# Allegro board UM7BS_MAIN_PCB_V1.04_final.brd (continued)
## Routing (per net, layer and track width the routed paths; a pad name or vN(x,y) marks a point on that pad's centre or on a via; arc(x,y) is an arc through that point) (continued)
N16952168: length 1.8
  TOP w0.102: CN9.38 v1(78.08,43.92)
  BOTTOM w0.102: R560.2 v1(78.08,43.92)
N16952170: length 1.8
  TOP w0.102: CN9.68 80.37,36.42 v1(80.46,36.32)
  BOTTOM w0.102: R561.2 80.56,36.42 v1(80.46,36.32)
N16952426: length 7.2
  TOP w0.124: C296.1 90.29,46.04 89.98,45.73 89.55,45.73 89.28,45.46 89.28,42.29 88.53,41.54 87.94,41.54 87.82,41.67 CN9.47
N16952428: length 7.3
  TOP w0.124: C171.1 89.77,47.1 88.89,47.1 88.38,46.58 88.38,43.27 88.15,43.04 87.77,43.04 87.64,43.17 CN9.41
N16952430: length 7.2
  TOP w0.124: CN9.49 87.82,41.17 87.94,41.29 88.63,41.29 89.53,42.18 89.53,45.35 89.65,45.48 90.07,45.48 C312.1
N16952432: length 7.1
  TOP w0.124: C263.1 89,46.85 88.63,46.48 88.63,43.16 88.25,42.79 87.82,42.79 87.7,42.67 CN9.43
N16952456: length 2.2
  TOP w0.102: CN9.69 89.09,36.17 R564.1
N16968122: length 16.8
  TOP w0.508: v1(111.5,88.7) R707.2 ; R707.2 R663.2 R495.2 R3100.2 ; R707.2 112.54,89.71 112.89,90.06 Q95.2
  BOTTOM w0.305: R3091.1 115.8,83.6 112.75,86.65 112.75,87.44 v1(111.5,88.7)
N16968198: length 12.8
  TOP w0.406: v1(112.61,91.07) 112.61,91.5 114.33,93.21 Q95.1
  BOTTOM w0.305: R606.2 115.6,84.48 113.43,86.65 113.43,88.91 112.61,89.73 v1(112.61,91.07)
N16969285: length 5.5
  BOTTOM w0.406: J5.5 109.26,95.31 108.84,95.72 107.7,95.72 106.12,94.15 R367.1
N16969287: length 4.7
  BOTTOM w0.406: J5.6 107.3,94.33 106.31,93.33 104.97,93.33 104.62,93.69 R3097.1
N16970384: length 4.2
  TOP w0.305: R3098.1 114.12,81.12 CN40.1 115.6,81.11 118.31,81.11 R681.2
N16970389: length 4.3
  TOP w0.305: R636.2 118.44,83.12 CN40.3 114.12,83.12 R465.1
N16970394: length 4.4
  TOP w0.305: R756.2 115.61,85.12 CN40.5 114.12,85.12 R466.1
N16970402: length 4.6
  TOP w0.305: R755.1 117.15,86.61 116.65,87.12 115.61,87.12 CN40.7 115.6,87.12 R3099.1
N16987716: length 1.3
  TOP w0.102: R509.2 Q16.3
N16987732: length 8.1
  TOP w0.102: R509.1 100.31,10.12 100.72,9.71 104.27,9.71 105.48,8.5 LED2.2
N17079846: length 3.8
  TOP w1.016: v2(99.24,57.46) 99.48,57.23 CN3.P7
  BOTTOM w0.762: v2(99.24,57.46) 99.59,57.46 R748.2
N17211775: length 3.4
  BOTTOM w0.102: R467.2 45.06,57.63 45.06,58.25 45.47,58.66 U31.67
N17343515: length 2.8
  TOP w0.102: R170.2 180.23,87.06 179.98,87.31 179.98,87.69 179.54,88.13 U9.4
N17343556: length 2.5
  TOP w0.101: R578.1 170.18,88.02 170.75,88.02 170.86,88.13 U9.25
N17343558: length 2.6
  TOP w0.101: U9.26 170.97,87.48 170.66,87.79 170,87.79 R577.1
N17343560: length 1.4
  TOP w0.102: R175.2 179.87,94.63 U9.14
N17343567: length 2.1
  TOP w0.305: FB2.2 170.57,93.98 U9.16
N17343572: length 2.6
  TOP w0.203: R173.1 169.84,91.67 170.85,92.68 U9.18
N17343578: length 2.4
  TOP w0.305: U9.23 170.99,89.43 170.52,89.9 R171.1
N17555300: length 1.9
  BOTTOM w0.203: U53.4 155.01,52.26 R3107.2 R3106.1
N17555409: length 1.1
  BOTTOM w0.305: U53.6 151.39,50.64 R3108.1
N17556891: length 1.9
  BOTTOM w0.254: U2525.4 165.54,72.27 R746.1 166.51,72.44 R3113.2
N17556904: length 2.2
  BOTTOM w0.254: U2525.5 166.04,71.44 166.85,71.44
  BOTTOM w0.305: R3109.2 166.85,71.44
N17556998: length 1.3
  BOTTOM w0.305: U2525.6 166.57,68.79 166.95,69.17 R3112.1
N169681891: length 0.9
  BOTTOM w0.305: R3093.2 C727.2

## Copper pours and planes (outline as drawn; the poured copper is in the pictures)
+V1.2A on TOP (solid shape): 166.9,28.21 166.9,27.46 166.85,27.42 166.42,27.42 166.3,27.3 166.29,27.3 165.07,26.09 165.07,26.07 164.97,25.97 164.97,25.87 164.85,25.74 164.08,25.74 163.96,25.87 163.96,25.96 163.97,26.03 163.98,26.09 163.98,26.36 164.15,26.54 164.18,26.53 164.24,26.53 164.3,26.55 164.48,26.55 166.17,28.23 166.87,28.23
+V1.2A on BOTTOM (solid shape): 166.16,26.46 166.16,25.83 166.03,25.7 164.33,25.7 164.17,25.86 164.17,26.22 164.8,26.84 165.78,26.84
+V1.05A on TOP (solid shape): 164.88,13.93 167.51,13.93 167.9,13.55 167.9,10.9 167.8,10.8 163.9,10.8 162.79,11.91 162.79,14.48 162.99,14.68 164.14,14.68
+V1.05A on TOP (solid shape): 188.1,60.39 188.1,60.14 187.34,59.37 187.09,59.37 187.03,59.44 186.58,59.88 186.58,60.01 187.09,60.52 187.98,60.52
+V1.05A on TOP (solid shape): 188.1,65.09 188.1,64.84 187.98,64.71 187.09,64.71 186.6,65.2 186.6,65.24 186.58,65.28 186.58,65.34 186.71,65.47 186.71,65.85 186.58,65.98 186.58,66.11 186.71,66.23 186.96,66.23
+V1.05A on TOP (solid shape): 174.82,55.05 174.92,55.04 175.01,55.05 175.02,55.06 175.28,55.06 175.59,54.74 175.59,54.73 175.62,54.66 175.66,54.6 175.66,54.29 175.53,54.17 174.64,54.17 174.46,54.35 174.46,54.36 174.4,54.47 174.3,54.54 174.28,54.55 174.26,54.57 174.26,54.93 174.39,55.06 174.82,55.06
+V1.05A on TOP (solid shape): 179.46,61.28 179.48,61.27 179.49,61.26 179.75,61.14 180,61.26 180.01,61.27 180.04,61.28 180.23,61.28 180.36,61.15 180.36,60.14 180.05,59.83 179.99,59.8 179.94,59.76 179.92,59.76 179.72,59.76 179.21,60.26 179.21,61.15 179.34,61.28
+V1.05A on TOP (solid shape): 181.88,67.25 181.88,67.12 181.75,66.99 181.75,66.61 181.99,66.38 181.99,66.34 182.01,66.31 182.01,65.72 182.77,64.96 182.77,64.84 182.76,64.82 182.74,64.8 182.66,64.75 182.6,64.67 182.53,64.62 182.44,64.65 181.37,65.72 181.25,65.72 180.87,65.34 180.87,65.09 181.25,64.71 181.25,64.2 180.99,63.95 180.87,63.95 180.48,64.33 180.48,64.96 180.04,65.41 180.01,65.45 179.98,65.5 179.98,65.51 179.98,65.72 181.63,67.38 181.75,67.38
+V1.05A on BOTTOM (solid shape): 170.24,48.86 170.24,47.49 170.16,47.41 170.16,44.25 169.83,43.92 167.84,43.92 167.69,44.06 167.69,49.8 167.86,49.97 169.13,49.97
+V1.05A on BOTTOM (solid shape): 179.99,63.02 179.99,62.1 179.78,61.89 179.57,61.89 179.31,61.63 178.82,61.63 178.74,61.71 178.74,62.21 178.86,62.33 178.86,63.59 178.96,63.69 179.31,63.69
+V1.05A on BOTTOM (solid shape): 164.71,14.87 164.81,14.8 164.78,14.69 164.83,14.13 165.36,14.34 165.37,14.35 166.34,14.35 166.37,14.32 166.37,11.53 166.15,11.31 163.18,11.31 163.07,11.42 163.07,14.56 163.37,14.87
+V1.05A on LAY3 (solid shape): outline of 1400 points within 157.66,11.65 166.1,31.05
+V1.05A on LAY4 (solid shape): outline of 404 points within 158.47,27.78 169.86,49.4
+V1.05A on LAY4 (solid shape): outline of 964 points within 180.99,59.63 188.23,72.96
+V1.05A on VCC5 (solid shape): outline of 4249 points within 168.56,43.92 182.29,68.54
+V1.5S on BOTTOM (solid shape): 145.69,44.06 145.69,41.64 145.57,41.51 143.77,41.51 143.69,41.59 143.69,42.34 143.77,42.42 144.28,42.42 144.38,42.52 144.38,43.95 144.6,44.17 145.58,44.17
+V1.8A on TOP (solid shape): 154.41,47.45 155.05,47.45 155.18,47.32 155.18,45.67 154.8,45.29 153.91,45.29 153.27,45.92 152.64,45.92 152.51,46.05 152.51,47.7 152.64,47.83 154.03,47.83
+V1.8A on TOP (solid shape): 156.73,14.06 156.73,12.07 155.64,10.97 154.95,10.97 153.13,12.79 153.13,14.15 153.39,14.42 153.47,14.45 153.54,14.41 153.91,14.31 154.15,14.62 154.18,14.69 154.25,14.71 156.08,14.71
+V1.8A on BOTTOM (solid shape): 156.8,13.82 156.81,13.82 156.81,11.57 156.6,11.36 153.59,11.36 153.39,11.56 153.39,13.83 153.55,13.98 156.63,13.98
+V1.8A on BOTTOM (solid shape): 175.14,50.26 175.14,49.01 175.1,48.96 174.65,48.96 174.62,48.99 174.62,49.88 174.39,50.11 172.8,50.11 172.58,49.88 172.58,49.08 172.53,49.03 172.09,49.03 172.01,49.1 172.02,49.11 172.02,49.93 172.61,50.52 174.88,50.52
+V1.8A on BOTTOM (solid shape): outline of 318 points within 144.99,43.25 165.64,69.1
+V1.8A on LAY3 (solid shape): outline of 1597 points within 143.92,11.64 155.92,44.79
+V1.8A on LAY3 (solid shape): outline of 2990 points within 178.96,41.21 193.56,69.81
+V1.8A on LAY4 (solid shape): outline of 1638 points within 170.19,57.09 182.01,65.65
+V1.8A_SPI on TOP (solid shape): 157.08,49.15 157.08,47.19 156.19,46.3 156.19,43 155.81,42.62 152.64,42.62 152.51,42.75 152.51,44.42 152.56,44.46 154.73,44.46 155.43,45.16 155.43,47.96 155.18,48.21 154.41,48.21 154.29,48.34 154.29,49.35 154.35,49.42 156.81,49.42
+V1.15A on TOP (solid shape): 165.36,29.94 165.36,29.12 165.3,29.06 164.53,29.06 164.37,29.21 164.37,29.7 164.17,29.91 163.11,29.91 162.85,30.17 162.85,30.7 162.94,30.79 164.51,30.79
+V1.15A on TOP (solid shape): 187.31,63.6 187.36,63.54 187.47,63.44 187.47,63.31 187.34,63.18 186.96,63.18 186.64,63.51 186.6,63.55 186.55,63.59 186.34,63.8 186.34,63.82 186.3,63.92 186.22,64 186.2,64.02 186.2,64.05 186.2,64.2 186.33,64.33 186.58,64.33
+V1.15A on TOP (solid shape): 186.07,66.36 186.07,66.23 186.2,66.11 186.33,66.11 186.48,65.95 186.48,65.94 186.49,65.92 186.53,65.85 186.57,65.8 186.58,65.78 186.58,65.76 186.58,65.6 186.45,65.47 186.29,65.47 186.27,65.47 186.26,65.49 186.19,65.54 186.1,65.58 186.09,65.58 185.44,66.23 185.44,66.49 185.56,66.61 185.82,66.61
+V1.15A on TOP (solid shape): 186.5,59.76 186.52,59.75 186.54,59.73 186.61,59.67 186.69,59.62 186.7,59.62 187.05,59.27 187.06,59.27 187.47,58.87 187.47,58.76 187.45,58.74 187.44,58.73 187.38,58.69 187.33,58.63 187.31,58.62 187.29,58.61 187.09,58.61 187.04,58.67 187,58.7 186.2,59.5 186.2,59.63 186.33,59.76
+V1.15A on TOP (solid shape): 186.17,67.76 186.19,67.75 186.3,67.67 186.41,67.65 186.44,67.64 186.47,67.62 186.48,67.6 186.49,67.43 186.58,67.3 186.58,67.28 186.58,67.04 186.58,67.02 186.57,67 186.48,66.78 186.57,66.55 186.58,66.54 186.58,66.52 186.58,66.36 186.49,66.27 186.45,66.25 186.42,66.27 185.82,66.87 185.82,66.97 185.9,67.16 185.82,67.34 185.82,67.63 185.95,67.76
+V1.15A on BOTTOM (solid shape): outline of 202 points within 157.42,71.1 174.53,78.37
+V1.15A on BOTTOM (solid shape): outline of 887 points within 183.79,58.23 187.98,71.31
+V1.15A on LAY3 (solid shape): outline of 456 points within 185.44,63.31 188.15,69.41
+V1.15A on LAY4 (solid shape): outline of 807 points within 183.79,66.99 186.83,75
+V1.15S on TOP (solid shape): 165.33,28.46 165.33,27.68 165.24,27.58 164.4,27.58 164.05,27.23 163.88,27.23 163.66,27.01 163.45,27.01 163.39,27.08 163.39,27.99 163.52,28.12 164,28.12 164.41,28.54 165.26,28.54
+V1.24A on TOP (solid shape): 166.89,29.64 166.89,28.65 166.83,28.59 165.7,28.59 165.59,28.7 165.59,29.58 165.69,29.68 166.85,29.68
+V1.24A on TOP (solid shape): 180.68,67.76 180.7,67.75 180.72,67.74 180.92,67.65 181.12,67.74 181.14,67.75 181.16,67.76 181.37,67.76 181.5,67.63 181.5,67.5 180.99,66.99 180.87,66.99 180.61,67.25 180.48,67.25 180.23,66.99 180.1,66.99 179.98,67.12 179.98,67.25 180.48,67.76
+V1.24A on TOP (solid shape): 183.15,66.87 183.53,66.87 183.66,66.99 183.79,66.99 184.17,66.61 184.22,66.54 184.28,66.5 184.29,66.49 184.29,66.36 184.17,66.23 183.93,66.23 183.91,66.24 183.9,66.25 183.66,66.35 183.42,66.25 183.4,66.24 183.38,66.23 183.15,66.23 182.26,67.12 182.26,67.25 182.39,67.38 182.64,67.38
+V1.24A on BOTTOM (solid shape): 156.77,53.81 156.77,52.79 156.61,52.63 153.79,52.63 153.71,52.71 153.71,53.87 153.82,53.98 156.6,53.98
+V1.24A on LAY3 (solid shape): outline of 534 points within 179.74,61.79 183.79,68.9
+V1.24A on LAY4 (solid shape): 166.09,29.56 166.09,28.72 165.98,28.61 165.12,28.61 164.99,28.74 164.99,29.59 165.09,29.7 165.96,29.7
+V1.24A on LAY4 (solid shape): outline of 1237 points within 168.91,44.74 180.74,69.15
+V1P8A_EMMC on TOP (solid shape): 185.34,29.92 186.08,29.92 186.16,29.84 186.24,29.33 186.74,29.43 187.26,29.43 187.33,29.37 187.33,28.76 186.79,28.22 186.03,28.22 185.82,28.38 185.56,28.36 185.53,28.34 184.99,28.88 184.99,29.02 184.68,29.33 183.77,29.33 183.67,29.43 183.67,30.3 183.77,30.4 184.86,30.4
+V2P8A_EMMC on TOP (solid shape): outline of 93 points within 179.71,26.37 183.28,30.58
+V3.3A on TOP (solid shape): 156.58,93.16 156.58,90.66 155.97,90.04 153.95,90.04 153.88,90.11 153.88,90.96 154.02,91.1 155.28,91.1 155.53,91.35 155.53,93.24 155.69,93.4 156.34,93.4
+V3.3A on TOP (solid shape): outline of 116 points within 108.14,52.6 116.51,71.83
+V3.3A on BOTTOM (solid shape): 170.42,36.08 170.42,34.71 170.21,34.5 168.05,34.5 167.91,34.63 167.91,36.08 168.03,36.19 170.3,36.19
+V3.3A on BOTTOM (solid shape): 215.99,17.36 217.75,17.36 217.88,17.23 217.88,14.57 217.5,14.19 214.96,14.19 214.83,14.31 214.83,16.25 214.38,16.7 210.05,16.7 207.47,14.12 206.88,14.12 206.54,14.46 206.54,15.33 209.14,17.93 215.42,17.93
+V3.3A on BOTTOM (solid shape): 156.08,79.78 156.08,79 155.51,78.42 153.73,78.42 153.12,77.81 131.65,77.81 130.53,76.69 119.41,76.69 119.17,76.45 119.17,76.25 119.16,76.17 119.17,76.1 119.17,73.55 116.77,71.15 116.77,66.64 116.34,66.21 111.92,66.21 111.07,67.06 111.07,72.71 111.48,73.13 115.28,73.13 116.28,74.13 116.63,74.13 117.02,74.52 117.02,77.15 118.45,78.58 118.46,78.58 118.53,78.66 127.41,78.66 128,79.25 131.71,79.25 131.72,79.24 150.09,79.24 150.92,80.07 155.8,80.07
+V3.3A on BOTTOM (solid shape): 110.58,52.43 110.58,44.47 112.51,42.54 112.51,42.21 112.5,42.13 112.51,42.06 112.51,37.39 113.19,36.71 113.19,35.02 112.74,34.57 112.74,31.99 112.73,31.98 112.73,30.12 112.17,29.56 110.44,29.56 110.33,29.45 110.33,28.89 110.21,28.76 107.86,28.76 106.63,29.99 106.63,31.56 106.96,31.89 107,31.89 107.08,31.97 109.74,31.97 110.37,32.6 110.37,34.68 111.02,35.32 111.02,36.63 110.36,37.29 110.36,40.45 109.34,41.47 109.34,41.62 108.05,42.91 108.05,53.22 108.29,53.46 109.55,53.46
+V3.3A on LAY4 (solid shape): 156.94,92.61 156.94,85.74 156,84.81 156,79.33 155.77,79.1 155.37,79.1 155.14,79.33 155.14,85.22 156.09,86.17 156.09,92.31 155.42,92.98 155.42,93.29 155.68,93.55 155.99,93.55
+V3.3A on VCC5 (solid shape): outline of 122 points within 151.06,27.73 170.49,41.59
+V3.3A_KBC on BOTTOM (solid shape): 81.96,79.49 81.96,74.89 81.81,74.75 80.27,74.75 80.06,74.96 80.06,77.66 79.44,78.28 58.62,78.28 58.19,77.85 58.19,77.71 58.07,77.61 57.98,77.5 57.97,77.36 57.98,77.22 58.07,77.11 58.18,77.02 58.19,77.02 58.19,75.64 58.07,75.52 56.6,75.52 56.3,75.83 56.3,79.48 56.52,79.7 81.74,79.7
+V3.3A_KBC on LAY4 (solid shape): 58.59,76.12 58.68,76.07 58.68,75.97 58.95,75.39 59.23,75.97 59.22,76.07 59.31,76.12 59.59,76.12 59.65,76.06 59.65,75.9 59.65,75.89 59.62,75.68 59.72,75.49 59.9,75.4 60.09,75.41 60.18,75.4 60.22,75.32 60.22,72.44 59.99,72.21 56.35,72.21 56.33,72.19 47.69,72.19 46,70.5 46,68.54 45.58,68.12 45.08,68.12 44.23,68.97 44.23,72.82 45.49,74.07 50.39,74.07 50.47,74.03 50.49,73.94 50.82,73.48 51.16,73.94 51.17,74.03 51.26,74.07 52.46,74.07 53.77,75.39 53.8,75.4 54.12,75.49 54.22,75.81 54.22,75.83 54.51,76.12 54.51,76.12 54.72,76.33 58.39,76.33
+V3.3A_PRIME on BOTTOM (solid shape): 169.26,33.5 169.26,32.67 169.36,32.57 170.92,32.57 171.13,32.35 171.13,30.88 170.98,30.73 168.19,30.73 167.98,30.94 167.98,33.68 168.01,33.71 169.05,33.71
+V3.3A_SW on TOP (solid shape): 167.47,15.3 171.45,15.3 171.6,15.16 171.6,14.4 171.54,14.34 166.56,14.34 166.18,14.72 166.18,14.88 166.15,15.3 165.75,15.4 165.65,15.41 165.61,15.49 165.61,15.81 165.41,16 165.41,16.01 164.97,16.01 164.83,16.15 164.83,16.77 164.51,17.09 164.26,17.09 163.96,17.38 163.96,17.63 164.02,17.69 165.08,17.69
+V3.3A_WIFI on TOP (solid shape): 231.5,28.69 231.5,27.86 231.46,27.82 229.17,27.82 228.76,27.41 228.76,12.77 228.76,12.77 228.76,11.79 229.32,11.23 231.46,11.23 231.57,11.13 231.57,10.26 231.44,10.13 227.88,10.13 227.17,10.83 227.17,27.8 228.21,28.83 231.36,28.83
+V3.3A_WIFI on BOTTOM (solid shape): 229.49,28.79 229.49,28.21 229.35,28.07 227.38,28.07 227.21,27.9 226.11,27.9 225.9,28.11 225.9,28.76 226.04,28.9 229.38,28.9
+V3.3A_WIFI on BOTTOM (solid shape): 224.74,15.6 224.74,12.43 225.74,11.43 229.53,11.43 229.71,11.25 229.71,10.38 229.36,10.02 224.75,10.02 222.89,11.88 222.89,14.58 222.63,14.83 218.84,14.83 218.49,15.19 218.49,16.78 218.75,17.04 223.3,17.04
+V3.3S on TOP (solid shape): 66.72,33.4 66.72,32.95 60.53,26.76 60.53,25.12 60.3,24.89 59.14,24.89 59.06,24.96 59.06,27.85 65.12,33.91 66.21,33.91
+V3.3S on TOP (solid shape): 209.66,42.73 209.66,42.06 210.38,41.34 210.38,40.19 210.75,39.82 212.49,39.82 212.62,39.69 212.62,39.31 212.55,39.25 211.85,39.25 211.81,39.26 211.78,39.26 210.32,39.26 209.82,39.75 209.28,39.75 209.08,39.95 209.08,42.73 209.11,42.76 209.63,42.76
+V3.3S on TOP (solid shape): outline of 323 points within 111.36,29.19 129.65,44.97
+V3.3S on BOTTOM (solid shape): 116.03,33.51 116.03,32.61 115.85,32.43 114.18,32.43 114.16,32.43 114.14,32.44 114.06,32.53 114.06,33.5 114.19,33.64 115.91,33.64
+V3.3S on BOTTOM (solid shape): 210.44,40.93 210.44,39.69 210.19,39.44 209.86,39.44 209.55,39.13 209.55,37.63 210.01,37.18 213.49,37.18 215.22,35.45 218.06,35.45 218.18,35.32 218.18,34.33 217.84,33.98 214.47,33.98 212.83,35.62 209.16,35.62 208.82,35.96 208.82,40.07 209.88,41.14 210.24,41.14
+V3.3S on BOTTOM (solid shape): 139.8,87.6 140.27,87.21 140.74,87.6 140.75,87.65 142.2,87.65 142.35,87.5 142.35,85.98 142.14,85.77 139.53,85.77 139.36,85.94 139.36,87.5 139.51,87.65 139.79,87.65
+V3.3S on BOTTOM (solid shape): outline of 166 points within 163.18,89.03 225.09,104.81
+V3.3S on BOTTOM (solid shape): outline of 275 points within 34.21,40.5 108.91,99.07
+V3.3S on LAY3 (solid shape): 225.03,90.3 225.03,45.8 225.89,44.94 225.89,36.49 222.94,33.53 216.44,33.53 215.96,34.02 215.96,35.06 216.27,35.37 221.69,35.37 223.83,37.51 223.83,43.46 223.05,44.24 223.05,90.73 223.29,90.97 224.36,90.97
+V3.3S on LAY4 (solid shape): outline of 724 points within 91.81,86.29 142.37,89.04
+V3.3S on LAY4 (solid shape): outline of 910 points within 92.85,96.49 164.47,101.62
+V3.3S on VCC5 (solid shape): 214.03,103.31 214.03,101.76 213.41,101.14 211.76,101.14 207.51,96.89 204.79,96.89 204.63,97.05 204.63,98.7 204.98,99.06 207.89,99.06 210.17,101.35 210.17,103.05 210.94,103.82 213.53,103.82
+V3.3S_AUDIO on BOTTOM (solid shape): 33.98,41.99 33.98,39.14 33.83,38.99 32.81,38.99 32.68,39.12 32.68,41.9 32.93,42.14 33.83,42.14
+V3.3S_MSATA on TOP (solid shape): outline of 94 points within 76.06,48.76 80.23,56.49
+V3.3S_MSATA on TOP (solid shape): outline of 114 points within 61.1,25.21 80.21,36.06
+V5_PVDD on BOTTOM (solid shape): 28.45,43.98 28.45,43.73 28.45,39.25 28.45,38.79 28.26,38.6 27.28,38.6 27.28,38.6 27.01,38.6 26.9,38.7 26.9,42.7 26.55,43.05 26.55,43.95 26.72,44.12 28.31,44.12
+V5A on TOP (solid shape): 62.78,14.15 62.78,10.61 62.45,10.28 61.15,10.28 60.79,10.63 60.79,14.14 61.03,14.37 62.56,14.37
+V5A on TOP (solid shape): 137.42,76.81 137.42,67.2 137.2,66.98 132.67,66.98 132.35,67.3 132.35,73.83 132.88,74.36 132.88,76.89 133.27,77.28 136.94,77.28
+V5A on TOP (solid shape): 156.48,21.21 156.48,21.11 156.28,20.91 156.28,20.68 155.35,19.75 154.94,19.75 154.88,19.81 154.88,20.09 155.96,21.17 156.01,21.17 156.08,21.24 156.45,21.24
+V5A on TOP (solid shape): 41.9,19.76 41.9,17.87 41.89,17.86 41.89,16.05 41.89,15.82 41.76,15.7 40.6,15.7 40.5,15.8 40.5,17.38 40.23,17.66 39.77,17.66 39.42,18 39.42,19.73 39.58,19.88 41.78,19.88
+V5A on TOP (solid shape): outline of 231 points within 12.09,37.03 54.73,88.31
+V5A on BOTTOM (solid shape): 16.17,83.88 16.17,80.38 15.81,80.03 12.97,80.03 12.69,80.31 12.69,83.91 12.97,84.19 15.86,84.19
+V5A on BOTTOM (solid shape): 54.39,88.63 54.39,86.75 54.13,86.49 49.71,86.49 49.47,86.73 49.47,89.14 50.33,90 53.03,90
+V5A on BOTTOM (solid shape): 156.08,21.17 157.1,21.17 157.23,21.04 157.23,19.9 157.1,19.77 154.27,19.77 154.22,19.82 154.22,21.55 154.49,21.83 155.43,21.83
+V5A on BOTTOM (solid shape): 161.57,18.81 161.57,17.39 161.3,17.13 161.29,17.13 161.29,16.06 161.17,15.94 161.16,15.94 160.74,15.52 159.7,15.52 159.48,15.3 159.48,14.66 159.38,14.56 158.55,14.56 158.48,14.63 158.48,16.66 158.89,17.07 158.89,18.31 159.12,18.54 160.28,18.54 160.65,18.91 161.46,18.91
+V5A on BOTTOM (solid shape): outline of 1559 points within 40.66,10.55 137.27,76.95
+V5A on LAY4 (solid shape): outline of 326 points within 131.22,21.03 145.14,77.19
+V5A on VCC5 (solid shape): outline of 525 points within 137.18,15.98 161.38,22.75
+V5S on TOP (solid shape): outline of 288 points within 30.45,66.85 107.99,87.84
+V5S on TOP (solid shape): outline of 529 points within 140.22,69.5 155.03,86.49
+V5S on BOTTOM (solid shape): 30.83,46.22 30.83,43.45 30.6,43.21 28.84,43.21 28.73,43.33 28.73,46.02 29.14,46.44 30.62,46.44
+V5S on BOTTOM (solid shape): 96.14,63.4 96.14,60.53 95.85,60.24 92.6,60.24 92.39,60.44 92.39,62.74 89.02,66.11 89.02,67.73 89.43,68.14 91.4,68.14
+V5S on BOTTOM (solid shape): 151.72,72.86 151.72,69.26 151.24,68.79 142.33,68.79 141.97,69.15 139.72,69.15 139.56,69.31 139.56,72.88 140.01,73.33 151.24,73.33
+V5S on BOTTOM (solid shape): outline of 202 points within 105.74,79.49 142.39,85.88
+V5S on LAY3 (solid shape): 32.72,83.82 32.72,81.94 29.91,79.13 29.91,47.2 30.83,46.29 30.83,45.14 30.61,44.92 30.06,44.92 28.53,46.45 19.4,46.45 17.13,44.18 17.13,26.67 18.29,25.51 18.29,24.69 18.08,24.48 17.47,24.48 16.08,25.86 16.08,45.36 18.86,48.13 25.12,48.13 27,50.02 27,82.17 28.89,84.06 32.49,84.06
+V5S_HDD on TOP (solid shape): 102.5,56.35 102.5,55.56 102.47,55.53 99.94,55.53 99.89,55.48 99.89,55.23 99.93,55.19 102.46,55.19 102.51,55.13 102.51,54.32 102.45,54.25 97.01,54.25 96.84,54.42 96.84,56.09 97.17,56.43 102.43,56.43
+V5S_HDD on BOTTOM (solid shape): 98.59,61.8 98.59,56.04 99.02,55.61 100.69,55.61 100.8,55.5 100.8,54.55 100.7,54.45 97.33,54.45 97.03,54.75 97.03,61.77 97.22,61.96 98.43,61.96
AGND on BOTTOM (solid shape): 20.68,43.41 20.68,42.33 20.4,42.05 19.14,42.05 18.99,42.2 18.99,43.44 19.12,43.56 20.53,43.56
AGND on GND2 (solid shape): outline of 1108 points within 17.79,7.04 60.65,36.21
AGND on VCC5 (solid shape): outline of 1334 points within 16.77,11.87 38.58,43.58
GND on TOP (solid shape): 40.13,17.25 40.13,15.56 39.99,15.43 38.85,15.43 38.67,15.61 38.67,17.19 38.85,17.37 40,17.37
GND on TOP (solid shape): 64.8,14.06 64.8,10.41 64.56,10.16 63.34,10.16 63.15,10.35 63.15,14.07 63.33,14.25 64.61,14.25
GND on TOP (solid shape): 67.06,24.71 67.06,23.16 66.97,23.07 62.7,23.07 62.52,23.25 62.52,24.83 62.72,25.03 66.73,25.03
GND on TOP (solid shape): 67.11,12.94 67.11,11.17 66.98,11.05 65.53,11.05 65.34,11.23 65.34,12.93 65.58,13.17 66.88,13.17
GND on TOP (solid shape): 78.96,57.57 78.96,56.89 78.86,56.8 76,56.8 75.91,56.9 75.91,57.2 76.77,58.06 78.46,58.06
GND on TOP (solid shape): 79.87,22.65 79.87,20.09 79.59,19.81 77.37,19.81 77.08,20.1 77.08,22.5 77.42,22.84 79.68,22.84
GND on TOP (solid shape): 124.54,68.54 124.54,66.91 124.29,66.66 120.89,66.66 120.22,67.34 120.22,68.61 120.36,68.75 124.33,68.75
GND on TOP (solid shape): 128.35,20.29 128.35,17.58 128.12,17.36 121.9,17.36 121.71,17.55 121.71,20.51 121.93,20.73 127.9,20.73
GND on TOP (solid shape): 131.77,72.56 131.77,68.8 131.52,68.56 128.99,68.56 128.78,68.78 128.78,71.62 129.93,72.78 131.55,72.78
GND on TOP (solid shape): 133.74,96.48 133.74,94.18 133.56,94 132.15,94 132.02,94.13 132.02,96.57 132.13,96.67 133.54,96.67
GND on TOP (solid shape): 137.26,60.29 137.26,58.1 137,57.83 133.76,57.83 133.56,58.04 133.56,60.42 133.82,60.68 136.88,60.68
GND on TOP (solid shape): 142.15,103.75 142.15,102.09 141.94,101.87 137.04,101.87 136.88,102.03 136.88,103.9 137.01,104.03 141.88,104.03
GND on TOP (solid shape): 142.37,76.62 142.37,72.84 141.75,72.22 138.21,72.22 137.86,72.56 137.86,76.45 138.31,76.9 142.1,76.9
GND on TOP (solid shape): 151.06,42.73 151.06,40.95 150.9,40.79 146.95,40.79 146.67,41.07 146.67,42.98 146.86,43.17 150.62,43.17
GND on TOP (solid shape): 152.89,13.98 152.89,13.04 152.79,12.93 151.75,12.93 151.44,13.25 151.44,14.28 151.52,14.36 152.51,14.36
GND on TOP (solid shape): 160.26,45.8 160.26,43 160,42.75 156.57,42.75 156.45,42.88 156.45,45.92 156.57,46.05 160,46.05
GND on TOP (solid shape): 185.12,15.51 185.12,10.87 184.58,10.33 180.56,10.33 180.5,10.4 180.5,15.47 180.89,15.86 184.76,15.86
GND on TOP (solid shape): 193.63,19.52 193.63,18.6 193.35,18.32 190.05,18.32 189.91,18.47 189.91,19.51 190.04,19.64 193.5,19.64
GND on TOP (solid shape): 49.48,16.46 49.48,14.44 49.33,14.29 46.16,14.29 45.91,14.54 45.91,16.03 46.49,16.61 49.34,16.61
GND on TOP (solid shape): 205.74,93.46 205.74,82.39 205.21,81.85 200.92,81.85 200.77,82.01 200.77,89.76 204.69,93.69 205.52,93.69
GND on TOP (solid shape): 207.79,76.27 207.79,61.91 207.54,61.66 205.5,61.66 205.38,61.79 205.38,76.27 205.63,76.52 207.54,76.52
GND on TOP (solid shape): 64.25,18.3 65.75,18.3 65.87,18.18 65.87,17.52 65.75,17.4 63.19,17.4 63.08,17.51 63.08,18.37 63.17,18.46 64.09,18.46
GND on TOP (solid shape): 153.27,45.54 153.27,44.78 153.14,44.65 152.71,44.65 151.62,44.65 151.49,44.78 151.49,45.54 151.62,45.67 153.14,45.67
GND on TOP (solid shape): 155.55,40.25 155.55,38.91 155.47,38.83 154.81,38.83 154.59,39.05 154.59,40.17 154.74,40.32 155.48,40.32
GND on TOP (solid shape): 198.83,40.12 198.83,38.63 196.55,36.36 196.04,35.85 195.29,35.85 195.15,35.99 195.15,40.49 195.48,40.82 198.12,40.82
GND on TOP (solid shape): 119.8,102.85 119.8,100.75 119.53,100.48 115.88,100.48 115.34,101.02 111.19,101.02 110.94,101.27 110.94,102.96 111.17,103.19 119.46,103.19
GND on TOP (solid shape): 138.68,28.35 138.68,26.13 138.2,25.65 131.87,25.65 131.08,26.43 126.18,26.43 125.98,26.64 125.98,28.77 126.17,28.96 138.07,28.96
GND on TOP (solid shape): 184.52,32.13 184.52,30.9 184.37,30.76 181.6,30.76 181.47,30.89 181.47,31.97 181.81,32.31 184.34,32.31
GND on TOP (solid shape): 111.96,28.03 111.96,25.46 113.13,24.3 113.13,20.85 112.75,20.47 109.23,20.47 107.97,21.73 107.97,27.82 108.44,28.28 111.72,28.28
GND on TOP (solid shape): 118.69,57.91 118.69,54.58 118.5,54.39 113.73,54.39 113.41,54.71 113.41,59.8 113.63,60.01 116.58,60.01
GND on TOP (solid shape): 128.4,62.04 128.4,60.73 128.13,60.46 124.3,60.46 123.53,61.24 123.53,62.04 123.7,62.22 128.22,62.22
GND on TOP (solid shape): 140.86,18.25 140.86,16.13 140.74,16 138.17,16 138.06,16.12 138.06,17.58 138.17,17.69 139.68,17.69 139.8,17.82 139.8,18.25 139.92,18.37 140.74,18.37
GND on TOP (solid shape): 148.94,28.23 148.94,23.27 148.61,22.93 148.61,20.99 148.47,20.85 147.04,20.85 146.77,21.13 146.77,28.01 147.28,28.52 148.65,28.52
GND on TOP (solid shape): 193.88,13.8 193.88,12.71 195.09,11.5 195.09,9.11 194.86,8.88 190.64,8.88 190.36,9.16 190.36,13.89 190.44,13.97 191.3,13.97 191.52,14.19 193.49,14.19
GND on TOP (solid shape): 203.79,47.83 203.79,45.78 203.68,45.67 202.78,45.67 201.89,46.56 199.74,46.56 199.62,46.68 199.62,48.14 199.79,48.32 203.31,48.32
GND on TOP (solid shape): 210.44,37.47 211.71,37.47 212.51,36.66 212.51,34.3 212.18,33.96 207.99,33.96 207.43,34.52 207.43,37.99 208.08,38.64 209.26,38.64
GND on TOP (solid shape): 185.4,26.9 185.4,23.24 185.26,23.1 181.78,23.1 181.2,23.67 181.2,26.84 181.39,27.02 183.2,27.02 183.47,27.29 183.47,27.79 183.66,27.98 184.32,27.98
GND on TOP (solid shape): 148.72,35.01 148.72,32.51 149.2,32.03 149.77,32.03 149.77,32.03 152.68,32.03 152.76,31.95 152.76,30.05 152.58,29.87 151.79,29.87 150.85,28.93 147.07,28.93 144.96,31.03 144.96,34.81 145.24,35.08 148.65,35.08
GND on TOP (solid shape): 178.63,24.37 179.57,24.37 179.64,24.31 179.64,21.97 179.51,21.85 175.95,21.85 175.76,22.04 175.76,22.59 175.11,23.23 175.11,23.65 175.39,23.93 175.61,23.93 175.76,24.08 175.76,24.73 175.92,24.9 178.11,24.9
GND on TOP (solid shape): 198.49,19.93 198.49,19.68 198.67,19.5 199.46,19.5 199.47,19.49 199.59,19.49 199.59,19.48 200.09,19.48 200.31,19.26 200.31,15.86 200.05,15.61 197.1,15.61 196.93,15.77 196.93,15.95 196.95,15.96 196.95,19.87 197.11,20.03 198.38,20.03
GND on TOP (solid shape): 174.13,14.21 174.13,11.71 173.99,11.42 174.13,11.14 174.13,10.91 173.98,10.76 169.64,10.76 169.47,10.92 169.47,13.79 169.76,14.07 171.82,14.07 172.18,14.44 173.9,14.44
GND on TOP (solid shape): 126.36,83.13 126.36,78.03 126.36,76.19 125.13,74.96 119.11,74.96 118.83,75.24 118.83,79.76 118.85,79.78 119,79.92 119.05,80.12 119.05,80.14 119.23,80.33 120.06,80.33 120.56,80.83 120.56,82.23 121.42,83.09 122.4,83.09 122.97,83.66 125.83,83.66
GND on TOP (solid shape): 175.78,15.61 175.78,11.06 175.51,10.79 174.52,10.79 174.4,10.91 174.4,11.07 174.44,11.08 174.69,11.42 174.44,11.76 174.4,11.77 174.4,15.59 174.58,15.77 175.62,15.77
GND on TOP (solid shape): 143.21,94.56 143.21,87.59 142.63,87.01 142.05,87.01 141.76,87.12 141.46,87.02 141.45,87.01 141.29,87.01 141.28,87.02 140.98,87.12 140.69,87.01 140.12,87.01 139.95,87.18 139.95,93.48 139.55,93.87 139.55,94.71 139.69,94.84 142.93,94.84
GND on TOP (solid shape): 164.34,25.36 164.34,22.41 163.88,21.98 164.34,21.56 164.34,19.01 164.21,18.88 157.99,18.88 157.73,19.14 157.73,21.5 157.74,21.5 157.74,21.73 157.73,21.73 157.73,25.36 157.86,25.49 164.21,25.49
GND on TOP (solid shape): 171.79,50.33 171.85,50.32 171.92,50.29 172.05,49.99 172.35,49.86 172.38,49.79 172.46,49.57 172.67,49.46 172.67,49.41 172.58,49.32 171.69,49.32 171.49,49.51 171.49,49.52 171.25,49.76 171.25,50.16 171.34,50.25 171.49,50.25 171.58,50.34 171.72,50.34
GND on TOP (solid shape): 171.61,28.09 171.61,28.08 172.45,28.08 172.6,27.93 172.6,27.08 171.66,27.08 171.41,27.33 170.61,27.33 170.28,27.65 169.15,27.65 169.12,27.68 169.11,27.71 169.12,27.75 168.88,28.36 168.64,27.75 168.65,27.71 168.64,27.68 168.62,27.65 167.58,27.65 167.53,27.7 167.53,28.88 167.66,29.01 170.69,29.01
GND on TOP (solid shape): 189.08,42.67 189.08,39.73 188.53,39.19 188.53,37.24 188.48,37.18 188.42,37.2 188.36,37.2 188.3,37.19 188.26,37.18 186.77,37.18 186,36.42 186,32.23 185.91,32.14 184.93,32.14 184.57,32.5 182.09,32.5 181.69,32.9 181.69,36.46 182.31,37.09 184.65,37.09 184.65,37.03 184.65,36.98 184.67,36.93 184.69,36.88 184.72,36.84 184.76,36.8 184.8,36.77 184.85,36.74 184.89,36.72 184.95,36.71 185,36.71 185.05,36.71 185.1,36.72 185.15,36.74 185.2,36.77 185.24,36.8 185.27,36.84 185.3,36.88 185.33,36.93 185.34,36.98 185.35,37.03 185.35,37.09 185.34,37.14 185.33,37.19 185.3,37.24 185.27,37.28 185.24,37.32 185.2,37.35 185.15,37.38 185.1,37.4 185.05,37.41 185,37.41 184.95,37.41 184.89,37.4 184.85,37.38 184.8,37.35 184.76,37.32 184.72,37.28 184.69,37.24 184.67,37.19 184.65,37.14 184.65,37.09 182.31,37.09 182.32,37.1 184.31,37.1 185.55,38.34 185.55,41.66 186.61,42.73 189.02,42.73
GND on TOP (solid shape): 181.41,32.74 181.41,32.21 181.24,32.04 181.24,30.72 180.4,29.87 180.4,29.08 180.09,28.78 180.04,28.78 179.98,28.72 179.94,28.69 179.9,28.65 179.82,28.56 178.11,28.56 177.53,27.98 177.53,27.41 177.33,27.2 173.65,27.2 173.32,27.54 173.32,28.18 172.8,28.7 171.79,28.7 171.02,29.47 171.02,30.43 172.59,32 172.9,32 172.9,31.97 172.91,31.92 172.92,31.87 172.94,31.82 172.97,31.78 173.01,31.74 173.05,31.71 173.1,31.68 173.15,31.66 173.2,31.65 173.25,31.65 173.3,31.65 173.35,31.66 173.4,31.68 173.45,31.71 173.49,31.74 173.53,31.78 173.56,31.82 173.58,31.87 173.59,31.92 173.6,31.97 173.6,32.03 173.59,32.08 173.58,32.13 173.56,32.18 173.53,32.22 173.49,32.26 173.45,32.29 173.4,32.32 173.35,32.34 173.3,32.35 173.25,32.35 173.2,32.35 173.15,32.34 173.1,32.32 173.05,32.29 173.01,32.26 172.97,32.22 172.94,32.18 172.92,32.13 172.91,32.08 172.9,32.03 172.9,32 172.59,32 173.45,32.86 181.29,32.86
GND on TOP (solid shape): 42.43,15.35 42.6,15.34 44.53,15.34 45.9,13.96 48.65,13.96 48.9,13.72 48.9,9.29 48.44,8.83 42.57,8.83 38.98,11.93 42.25,15.36
GND on TOP (solid shape): 73.9,29.19 76.99,32.78 80.43,29.52 80.42,29.34 80.41,29.16 80.41,24.56 79.84,23.99 77.67,23.99 76.54,22.86 76.54,22.08 75.6,21.14 73.59,21.14 73.18,21.55 73.18,26.71 73.9,27.43
GND on TOP (solid shape): 105.7,22.52 105.7,20.27 105.72,20.24 105.72,19.32 109.12,15.92 109.12,14.4 106.03,10.81 102.6,14.08 102.6,14.25 102.62,14.43 102.62,19.78 102.61,19.79 102.61,22.61 102.87,22.87 105.35,22.87
GND on TOP (solid shape): 92.54,10.01 92.63,9.95 92.6,9.83 93.5,7.25 94.41,9.83 94.38,9.95 94.47,10.01 98.67,10.01 100.85,7.83 102.59,7.83 102.72,7.7 102.72,7.17 102.56,7.01 61.38,7.01 60.98,7.41 60.98,9.72 61.28,10.01
GND on TOP (solid shape): 176.16,41.06 176.49,40.84 176.82,41.06 176.83,41.09 177.87,41.09 178.06,40.9 178.06,40.5 177.18,39.62 177.12,39.62 177.11,39.63 177.04,39.7 176.95,39.75 176.76,39.78 176.59,39.69 176.52,39.67 176.46,39.7 176.17,39.78 175.93,39.62 174.76,39.62 174.75,39.66 174.4,39.98 174.05,39.66 174.05,39.62 171.96,39.62 171.95,39.62 171.53,39.62 171.46,39.65 171.42,39.72 170.96,40.03 170.78,39.51 170.8,39.47 170.39,39.06 170.39,37.85 169.68,37.15 166.74,37.15 166.64,37.25 166.64,40.97 166.76,41.09 176.15,41.09
GND on TOP (solid shape): 188.07,76.27 188.11,76.25 188.12,76.21 188.12,75.96 187.89,75.73 187.89,75.25 187.88,75.23 187.87,75.21 187.8,75.03 187.93,74.77 187.9,74.7 187.89,74.65 187.89,74.55 187.88,74.53 187.87,74.51 187.8,74.31 187.92,74.13 187.96,74.05 187.92,73.96 187.83,73.87 187.8,73.75 187.75,73.67 187.66,73.66 187.55,73.68 187.45,73.66 187.36,73.67 187.31,73.75 187.28,73.87 187.19,73.96 187.14,74.05 187.19,74.13 187.31,74.31 187.24,74.51 187.24,74.51 187.24,74.55 187.28,74.6 187.32,74.6 187.34,74.58 187.57,74.44 187.79,74.62 187.79,74.63 187.82,74.65 187.84,74.65 187.8,74.69 187.79,74.71 187.72,74.86 187.56,74.92 187.56,74.92 187.53,74.95 187.53,75.12 187.56,75.15 187.56,75.15 187.72,75.22 187.78,75.38 187.78,75.47 187.71,75.63 187.53,75.69 187.48,75.7 187.44,75.74 187.44,75.92 187.77,76.25 187.78,76.25 187.87,76.24 187.96,76.26 187.97,76.27
GND on TOP (solid shape): outline of 174 points within 106.68,7.01 147.19,11.42
GND on TOP (solid shape): 191.29,72.42 191.38,72.42 191.5,72.38 191.62,72.4 191.69,72.39 191.74,72.34 191.96,72.19 192.19,72.31 192.26,72.35 192.34,72.33 192.36,72.32 192.38,72.28 192.36,72.24 192.31,72.2 192.27,72.15 192.26,72.13 192.23,72.13 192.15,72.13 192.03,72 192.01,71.99 191.99,71.99 191.81,71.93 191.7,71.72 191.67,71.71 191.32,71.46 191.52,71.08 191.58,71.03 191.59,70.96 191.58,70.91 191.59,70.86 191.56,70.77 191.47,70.74 191.41,70.75 191.35,70.75 191.25,70.78 191.23,70.87 191.19,71.09 190.98,71.19 190.95,71.2 190.84,71.31 190.84,71.35 190.86,71.4 190.91,71.41 191.24,71.62 190.95,71.9 190.88,71.92 190.84,71.99 190.87,72.08 190.95,72.11 191.14,72.16 191.24,72.34
GND on TOP (solid shape): 189.69,69.57 189.74,69.49 189.79,69.36 189.9,69.28 189.96,69.21 189.93,69.11 190.16,68.68 190.21,69.17 190.15,69.24 190.17,69.34 190.21,69.38 190.23,69.43 190.3,69.47 190.33,69.41 190.4,69.18 190.72,69.08 190.75,68.99 190.74,68.92 190.76,68.84 190.75,68.76 190.69,68.71 190.49,68.56 190.45,68.32 190.43,68.22 190.33,68.19 190.16,68.17 190.05,68.04 190.05,68.03 189.99,67.97 189.89,67.94 189.82,68.01 189.79,68.08 189.74,68.14 189.7,68.21 189.73,68.29 189.78,68.69 189.39,68.83 189.3,68.84 189.26,68.92 189.22,69.04 189.14,69.13 189.09,69.21 189.14,69.3 189.19,69.34 189.23,69.4 189.39,69.56 189.41,69.57 189.43,69.57 189.52,69.56 189.61,69.58
GND on TOP (solid shape): 189.27,75.08 189.32,75.16 189.41,75.16 189.45,75.15 189.49,75.15 189.52,75.12 189.52,74.95 189.49,74.92 189.49,74.92 189.3,74.54 189.72,74.58 189.73,74.6 189.77,74.6 189.81,74.55 189.81,74.51 189.74,74.31 189.86,74.13 189.91,74.05 189.86,73.96 189.82,73.93 189.79,73.9 189.73,73.87 189.66,73.88 189.52,73.92 189.37,73.9 189.36,73.9 189.23,73.9 189.21,73.9 189.19,73.91 189.17,73.94 189.14,73.96 189.09,74.05 189.14,74.13 189.02,74.58 188.88,74.14 188.92,74.05 188.87,73.96 188.8,73.9 188.76,73.82 188.71,73.76 188.62,73.76 188.52,73.79 188.41,73.78 188.35,73.78 188.3,73.83 188.2,73.93 188.2,74.16 188.28,74.33 188.21,74.51 188.21,74.55 188.25,74.6 188.29,74.6 188.31,74.58 188.58,74.44 188.77,74.68 188.77,74.7 188.78,74.72 188.87,74.8 188.89,74.82 188.92,74.81 189.15,74.84 189.26,75.06
GND on TOP (solid shape): 194.11,64.96 194.19,64.91 194.37,64.8 194.57,64.87 194.59,64.88 194.61,64.88 194.66,64.88 194.7,64.87 194.71,64.83 194.71,64.82 194.69,64.79 194.68,64.78 194.53,64.43 194.91,64.38 194.93,64.39 194.95,64.4 195.04,64.4 195.07,64.37 195.11,64.41 195.19,64.44 195.26,64.4 195.34,64.34 195.44,64.32 195.53,64.32 195.67,64.38 195.77,64.54 195.8,64.56 196.29,64.56 196.36,64.49 196.36,63.94 196.34,63.9 196.31,63.88 196.16,63.88 195.83,64.22 195.31,64.22 195.29,64.22 195.2,64.28 195.12,64.31 195.11,64.31 195.07,64.34 195.07,64.33 195.05,64.3 195.03,64.3 194.86,64.12 194.94,63.88 194.95,63.88 194.95,63.85 194.94,63.81 194.9,63.79 194.85,63.79 194.84,63.8 194.69,63.82 194.56,63.74 194.51,63.72 194.47,63.74 194.46,63.76 194.45,63.81 194.48,63.84 194.58,64.22 194.19,64.19 194.11,64.14 194.02,64.19 193.94,64.27 193.82,64.31 193.74,64.36 193.74,64.45 193.76,64.56 193.75,64.67 193.77,64.75 193.84,64.79 193.94,64.83 194.02,64.91
GND on TOP (solid shape): 191.18,74.95 191.22,74.96 191.26,74.95 191.29,74.92 191.29,74.88 191.27,74.85 191.3,74.48 191.66,74.58 191.67,74.59 191.71,74.61 191.74,74.59 191.76,74.58 191.77,74.56 192.01,74.3 192.26,74.52 192.31,74.6 192.4,74.6 192.48,74.58 192.57,74.58 192.58,74.58 192.6,74.57 192.61,74.56 192.63,74.53 192.61,74.49 192.55,74.43 192.53,74.43 192.33,74.35 192.23,74.17 192.17,74.1 192.08,74.1 191.81,74.06 191.73,73.79 191.71,73.69 191.61,73.66 191.54,73.67 191.46,73.66 191.45,73.66 191.43,73.67 191.2,73.9 191.19,73.9 191.14,73.94 191.11,73.97 191.05,74.05 191.1,74.14 191.08,74.54 190.72,74.38 190.67,74.31 190.59,74.3 190.48,74.3 190.37,74.27 190.28,74.28 190.22,74.36 190.2,74.44 190.14,74.53 190.14,74.55 190.14,74.6 190.15,74.64 190.19,74.65 190.22,74.64 190.24,74.62 190.58,74.46 190.65,74.84 190.64,74.85 190.64,74.9 190.69,74.94 190.73,74.94 190.74,74.93 190.96,74.8 191.17,74.93
GND on TOP (solid shape): outline of 224 points within 187.81,71.15 190.2,72.17
GND on TOP (solid shape): outline of 92 points within 193.28,69.73 196.36,71.27
GND on TOP (solid shape): outline of 292 points within 0.27,7.01 29.59,105.16
GND on TOP (solid shape): outline of 121 points within 185.33,65.72 189.18,68.92
GND on TOP (solid shape): outline of 495 points within 193.71,65.12 196.36,69.42
GND on TOP (solid shape): outline of 742 points within 43.06,7.01 245.9,105.19
GND on TOP (solid shape): outline of 1137 points within 183.05,68.62 187.3,74.65
GND on TOP (solid shape): outline of 1542 points within 170.83,50.51 178.41,57.4
GND on TOP (solid shape): outline of 16588 points within 171.32,48.58 196.36,76.27
GND on BOTTOM (solid shape): 162.46,20.74 160.18,20.74 160.18,23.54 162.46,23.54
GND on BOTTOM (solid shape): 114.2,40.51 114.2,36.71 113.49,36.71 112.8,37.4 112.8,40.51 112.93,40.63 114.07,40.63
GND on BOTTOM (solid shape): 12.37,82.43 12.37,80.4 12.24,80.27 10.65,80.27 10.49,80.43 10.49,82.47 10.66,82.64 12.16,82.64
GND on BOTTOM (solid shape): 20.55,45.09 20.55,43.94 20.41,43.79 19.03,43.79 18.95,43.87 18.95,45.2 19.07,45.32 20.32,45.32
GND on BOTTOM (solid shape): 28.49,45.64 28.49,44.37 28.4,44.27 26.86,44.27 26.68,44.45 26.68,45.75 26.75,45.82 28.32,45.82
GND on BOTTOM (solid shape): 30.43,42.83 30.43,40.07 29.44,39.07 28.75,39.07 28.71,39.11 28.71,42.88 28.83,43 30.26,43
GND on BOTTOM (solid shape): 57.54,81.17 57.54,79.98 57.45,79.88 56.57,79.88 56.41,80.04 56.41,81.15 56.52,81.25 57.46,81.25
GND on BOTTOM (solid shape): 96.72,59.75 96.72,54.79 96.53,54.6 94.31,54.6 94.12,54.79 94.12,59.64 94.39,59.92 96.55,59.92
GND on BOTTOM (solid shape): 106.15,74.07 106.15,71.99 105.92,71.75 103.72,71.75 103.4,72.06 103.4,73.81 103.9,74.31 105.92,74.31
GND on BOTTOM (solid shape): 122.09,62.52 122.09,61 121.96,60.87 120.44,60.87 120.31,61 120.31,62.52 120.44,62.65 121.96,62.65
GND on BOTTOM (solid shape): 141.17,42.77 141.17,41.76 141.06,41.65 140.27,41.65 140.19,41.73 140.19,42.82 140.23,42.86 141.08,42.86
GND on BOTTOM (solid shape): 143.83,76.48 143.83,73.78 143.57,73.52 137.64,73.52 137.44,73.73 137.44,76.6 137.61,76.77 143.54,76.77
GND on BOTTOM (solid shape): 146.81,48.5 146.81,47.18 146.67,47.04 145.31,47.04 145.2,47.15 145.2,47.58 146.19,48.56 146.74,48.56
GND on BOTTOM (solid shape): 147.14,43.38 147.14,41.7 147.02,41.58 146.04,41.58 145.88,41.74 145.88,43.43 145.97,43.51 147,43.51
GND on BOTTOM (solid shape): 150.65,55.85 150.65,54.35 150.51,54.22 149.71,54.22 149.53,54.39 149.53,55.46 150.01,55.93 150.56,55.93
GND on BOTTOM (solid shape): 153.02,14 153.02,11.71 152.83,11.52 152.53,11.52 151.81,12.24 151.81,14.01 151.93,14.13 152.88,14.13
GND on BOTTOM (solid shape): 157.41,85.14 157.41,81.02 157.14,80.76 154.82,80.76 154.64,80.93 154.64,85.21 154.83,85.41 157.15,85.41
GND on BOTTOM (solid shape): 158.83,13.62 158.83,11.53 158.67,11.37 157.16,11.37 157.01,11.52 157.01,13.62 157.15,13.76 158.7,13.76
GND on BOTTOM (solid shape): 162.28,13.86 162.28,11.54 162.13,11.39 159.8,11.39 159.54,11.64 159.54,14.18 159.67,14.31 161.83,14.31
GND on BOTTOM (solid shape): 162.88,73.6 162.88,72.4 162.72,72.24 160.89,72.24 160.64,72.49 160.64,73.65 160.78,73.79 162.7,73.79
GND on BOTTOM (solid shape): 167.18,49.8 167.18,43.99 167.11,43.93 166.12,43.93 165.58,44.47 165.58,49.66 165.76,49.85 167.13,49.85
GND on BOTTOM (solid shape): 171.06,30.3 171.06,28.6 170.74,28.27 170.32,28.27 169.31,29.29 169.31,30.25 169.51,30.46 170.91,30.46
GND on BOTTOM (solid shape): 194.96,19.43 194.96,17.02 194.67,16.73 190.53,16.73 190.25,17 190.25,19.33 190.48,19.55 194.85,19.55
GND on BOTTOM (solid shape): 199.66,78.93 199.66,77.41 199.53,77.28 195.98,77.28 195.72,77.54 195.72,78.81 196.23,79.31 199.28,79.31
GND on BOTTOM (solid shape): 213.76,39.82 213.76,39.18 213.63,39.05 210.81,39.05 210.71,39.15 210.71,39.82 210.84,39.94 213.63,39.94
GND on BOTTOM (solid shape): 52.89,85.83 52.89,84.06 52.64,83.81 50.14,83.81 49.89,84.06 49.89,85.93 50.12,86.15 52.57,86.15
GND on BOTTOM (solid shape): 160.9,25.34 160.9,24.66 160.65,24.4 158.49,24.4 158.36,24.53 158.36,25.34 158.48,25.47 160.78,25.47
GND on BOTTOM (solid shape): 170.45,39.61 170.45,36.82 170.22,36.58 168.81,36.58 168.6,36.8 168.6,39.58 168.82,39.8 170.26,39.8
GND on BOTTOM (solid shape): 229.26,12.58 229.26,11.81 229.07,11.62 226,11.62 225.7,11.92 225.7,12.93 225.81,13.04 228.8,13.04
GND on BOTTOM (solid shape): 147.57,68.02 147.57,65.13 147.35,64.9 142.83,64.9 142.27,65.46 142.27,68.34 142.43,68.5 147.09,68.5
GND on BOTTOM (solid shape): 155.91,55.95 155.91,54.45 155.78,54.32 154.97,54.32 154.8,54.49 154.8,55.56 154.8,55.56 154.8,55.91 154.92,56.03 155.83,56.03
GND on BOTTOM (solid shape): 222.56,14.47 222.56,13.21 221.92,12.57 220.68,12.57 220.44,12.81 220.44,14.11 220.55,14.21 220.55,14.22 221.48,14.22 221.81,14.55 222.47,14.55
GND on BOTTOM (solid shape): 26.6,36.75 26.6,32.86 26.59,32.83 26.55,32.81 23.17,32.81 23.05,32.94 23.05,36.62 23.3,36.87 26.48,36.87
GND on BOTTOM (solid shape): 120.19,103.36 120.19,100.3 119.81,99.92 113.7,99.92 112.91,100.72 110.23,100.72 110.08,100.87 110.08,103.36 110.41,103.68 119.86,103.68
GND on BOTTOM (solid shape): 123.09,40.76 123.09,36.49 123.07,36.46 123.04,36.44 118.77,36.44 118.64,36.57 118.64,40.63 118.9,40.89 122.96,40.89
GND on BOTTOM (solid shape): 170.11,14.34 171.15,14.34 171.24,14.25 171.24,11.83 170.9,11.49 167.37,11.49 167.14,11.72 167.14,15.06 167.28,15.2 169.25,15.2
GND on BOTTOM (solid shape): 174.41,49.9 174.41,47.48 174.18,47.26 172.86,47.26 172.71,47.4 172.71,47.72 172.89,47.89 173.57,47.89 173.7,48.03 173.7,49.87 173.8,49.96 174.35,49.96
GND on BOTTOM (solid shape): 221.48,38.63 221.48,36.74 221.12,36.39 219.98,36.39 219.77,36.59 219.77,37.43 219.88,37.53 220.24,37.53 220.36,37.66 220.36,38.67 220.49,38.8 221.3,38.8
GND on BOTTOM (solid shape): 16.16,92.02 19.74,92.02 20.05,91.71 20.05,87.83 19.65,87.43 15.94,87.43 15.58,87.78 15.58,90.63 13.86,92.35 13.86,93.04 13.93,93.1 15.08,93.1
GND on BOTTOM (solid shape): 116.74,76.62 116.74,74.51 116.66,74.43 116.08,74.43 115.11,73.46 113.78,73.46 113.57,73.67 113.57,75.62 114.91,76.97 116.39,76.97
GND on BOTTOM (solid shape): 228.86,27.76 228.86,26.87 228.27,26.28 226.23,26.28 226.23,26.28 225.82,26.28 225.56,26.54 225.56,27.31 225.66,27.41 226.97,27.41 227.44,27.88 228.75,27.88
GND on BOTTOM (solid shape): 153.75,23.52 153.75,23.06 153.6,22.91 153.6,22.04 153.96,21.69 153.96,20.94 153.92,20.91 153.06,20.91 152.23,21.74 152.23,22.76 153.28,23.8 153.46,23.8
GND on BOTTOM (solid shape): 161.72,69.73 161.72,67.83 161.62,67.73 160.29,67.73 160.2,67.78 160.09,67.79 160.07,67.79 159.86,68 159.86,69.72 159.97,69.83 161.62,69.83
GND on BOTTOM (solid shape): 167.8,29.77 167.8,29.43 168,29.22 168.21,29.22 168.51,28.92 168.51,28.58 168.05,28.12 166.53,28.12 166.27,28.38 166.27,29.93 166.35,30 167.57,30
GND on BOTTOM (solid shape): 158.18,38.53 159.28,38.53 159.5,38.3 159.5,36.64 159.37,36.51 152.37,36.51 151.9,36.98 151.9,38.46 152.06,38.63 156.15,38.63 156.51,38.98 157.72,38.98
GND on BOTTOM (solid shape): 186.47,43.41 186.47,42.54 186.94,42.07 187.07,41.94 187.07,39.9 186.92,39.75 185.19,39.75 185.05,39.88 185.05,43.35 185.25,43.55 186.33,43.55
GND on BOTTOM (solid shape): 114.17,35.26 115.61,35.26 115.67,35.21 115.67,33.94 115.54,33.81 114,33.81 113.88,33.69 113.88,32.45 113.88,32.45 113.88,32.11 113.81,32.03 113.01,32.03 112.91,32.13 112.91,34.45 113.37,34.91 113.37,35.5 113.47,35.6 113.83,35.6
GND on BOTTOM (solid shape): 178.58,62.9 178.58,62.39 178.46,62.27 178.46,61.68 178.62,61.52 179.43,61.52 179.62,61.71 179.83,61.71 179.99,61.55 179.99,61.47 179.36,60.84 178.98,60.84 178.7,60.55 178.42,60.55 178,60.98 178,61.49 177.84,61.65 177.84,62.53 178.25,62.94 178.54,62.94
GND on BOTTOM (solid shape): 129.64,88.95 129.64,87.49 129.87,87.26 129.87,87.22 129.91,87.22 130.22,86.91 130.22,86.12 130.38,85.96 130.38,84.46 130.4,84.43 130.4,84.35 131.17,83.58 134.01,83.58 134.35,83.93 135.12,83.93 135.18,83.87 135.18,82.38 135.07,82.27 130.29,82.27 128.78,83.78 128.78,85.17 128.62,85.33 128.62,89.06 128.73,89.17 129.42,89.17
GND on BOTTOM (solid shape): 153.04,16.98 153.29,16.88 153.53,16.98 154.43,16.98 154.56,16.85 154.56,15.84 154.43,15.71 152.9,15.71 152.76,15.79 152.59,15.8 152.58,15.8 152.56,15.81 152.53,15.84 152.53,16.85 152.65,16.98
GND on BOTTOM (solid shape): 171.75,47.23 171.75,44.57 171.65,44.47 170.58,44.47 170.4,44.65 170.4,46.78 170.45,46.87 170.55,46.87 170.95,46.91 171.05,47.3 171.07,47.39 171.15,47.44 171.54,47.44
GND on BOTTOM (solid shape): 158.28,18.2 158.28,17.42 158.25,17.34 158.17,17.32 157.78,16.97 158.17,16.62 158.25,16.59 158.28,16.52 158.28,14.19 158.03,13.94 157.19,13.94 157.09,14.04 157.09,16.68 157.19,16.77 157.19,18.1 157.39,18.31 158.18,18.31
GND on BOTTOM (solid shape): outline of 99 points within 33.59,84.94 38.53,92.77
GND on BOTTOM (solid shape): outline of 552 points within 216.81,58.74 219.98,77.41
GND on BOTTOM (solid shape): outline of 1995 points within 0.3,7.01 245.9,105.2
GND on GND2 (solid shape): outline of 60134 points within 0.27,7.01 245.9,105.19
GND on LAY3 (solid shape): outline of 811 points within 195.58,10.5 234.45,40.69
GND on LAY3 (solid shape): outline of 2330 points within 0.27,7.01 245.9,105.19
GND on LAY4 (solid shape): outline of 3181 points within 0.27,7.01 245.9,105.19
GND on VCC5 (solid shape): 22.67,33.3 22.02,33.3 22.02,36.26 22.67,36.26
GND on VCC5 (solid shape): outline of 47989 points within 0.27,7.01 245.9,105.19
GND_EARTH on TOP (solid shape): 82.76,23.1 82.76,19.76 82.47,19.46 80.23,19.46 80.13,19.56 80.13,23.16 80.29,23.32 82.54,23.32
GND_EARTH on BOTTOM (solid shape): 96.86,31.64 97.59,31.64 98.46,30.77 98.46,28.25 98.34,28.13 96.28,28.13 96.08,28.32 96.08,29.98 95.63,30.43 95.63,32.17 95.71,32.25 96.25,32.25
GND_EARTH on GND2 (solid shape): outline of 743 points within 80.15,11.2 100.74,41.19
GND_EARTH on LAY3 (solid shape): outline of 743 points within 80.15,11.2 100.74,41.19
GND_EARTH on LAY4 (solid shape): outline of 743 points within 80.15,11.2 100.74,41.19
GND_EARTH on VCC5 (solid shape): outline of 743 points within 80.15,11.2 100.74,42.22
VCC1_USB3.0 on BOTTOM (solid shape): 13.62,92.98 13.62,92.13 15.21,90.54 15.21,85.13 15.17,85.09 13.4,85.09 13.03,85.45 13.03,86.14 11.06,88.11 11.06,91.52 11.62,91.52 11.62,91.47 11.63,91.42 11.64,91.37 11.67,91.32 11.7,91.28 11.73,91.24 11.77,91.21 11.82,91.18 11.87,91.16 11.92,91.15 11.97,91.15 12.02,91.15 12.08,91.16 12.12,91.18 12.17,91.21 12.21,91.24 12.25,91.28 12.28,91.32 12.3,91.37 12.32,91.42 12.32,91.47 12.32,91.52 12.32,91.58 12.3,91.63 12.28,91.68 12.25,91.72 12.21,91.76 12.17,91.79 12.12,91.82 12.08,91.84 12.02,91.85 11.97,91.85 11.92,91.85 11.87,91.84 11.82,91.82 11.77,91.79 11.73,91.76 11.7,91.72 11.67,91.68 11.64,91.63 11.63,91.58 11.62,91.52 11.06,91.52 11.06,92.93 11.37,93.24 13.37,93.24
VCC2_USB3.0 on BOTTOM (solid shape): 40.32,92.23 40.32,90.76 42.05,89.03 48.53,89.03 48.77,88.79 48.77,87.05 48.77,87.05 48.77,85.99 48.16,85.39 39.58,85.39 39.02,85.94 39.02,87.08 38.07,88.03 38.07,89.58 38.18,89.83 38.07,90.09 38.07,90.14 37.54,90.67 37.54,92.32 37.77,92.55 40,92.55
VCC_LX on TOP (solid shape): 180.84,24.02 180.84,23.67 181.7,22.81 183.1,22.81 183.4,22.52 183.4,17.34 182.72,16.66 181.28,16.66 179.3,18.64 174.31,18.64 174.18,18.76 174.18,21.05 174.31,21.18 179.39,21.18 179.93,21.72 179.93,24.06 179.99,24.11 180.75,24.11
VCC_USB2 on TOP (solid shape): 45.37,18.17 52.81,18.17 53.47,17.5 53.47,16.64 53.18,16.35 51.88,16.35 51.39,16.84 43.55,16.84 42.32,18.07 42.32,19.61 42.45,19.74 43.79,19.74
VCC_USB3 on TOP (solid shape): 68.96,17.94 68.96,16.63 68.58,16.25 67.86,16.25 66.47,14.86 63.18,14.86 62.91,15.14 60.96,15.14 60.88,15.22 60.88,16.98 61.12,17.22 66.22,17.22 67.17,18.16 68.74,18.16
VDD10 on TOP (solid shape): outline of 565 points within 115.9,30.6 128.47,47.29
VDD10 on BOTTOM (solid shape): 124.02,47.1 124.02,46.18 123.92,46.08 122.19,46.08 122.05,46.22 122.05,47.11 122.18,47.24 123.88,47.24
VDD10 on BOTTOM (solid shape): 128.93,32.51 128.93,29.84 128.8,29.71 127.03,29.71 126.9,29.84 126.9,30.98 126.77,31.11 125.12,31.11 124.99,31.24 124.99,32.63 125.12,32.76 128.68,32.76
VDD10 on BOTTOM (solid shape): 114.71,40.75 114.89,40.7 115.08,40.73 115.11,40.74 115.34,40.51 115.37,40.44 115.34,40.37 115.25,40.06 115.45,39.8 115.47,39.78 115.47,39.24 115.46,39.21 115.43,39.19 115.19,38.86 115.43,38.52 115.46,38.5 115.47,38.47 115.47,37.89 115.45,37.85 115.44,37.85 115.29,37.56 115.44,37.28 115.45,37.27 115.47,37.23 115.47,36.96 115.23,36.72 114.65,36.72 114.45,36.91 114.45,40.63 114.58,40.76 114.7,40.76
VDD12 on BOTTOM (solid shape): 158.98,88.18 158.98,86.81 158.88,86.71 154.37,86.71 154.27,86.81 154.27,88.17 154.35,88.25 158.91,88.25
